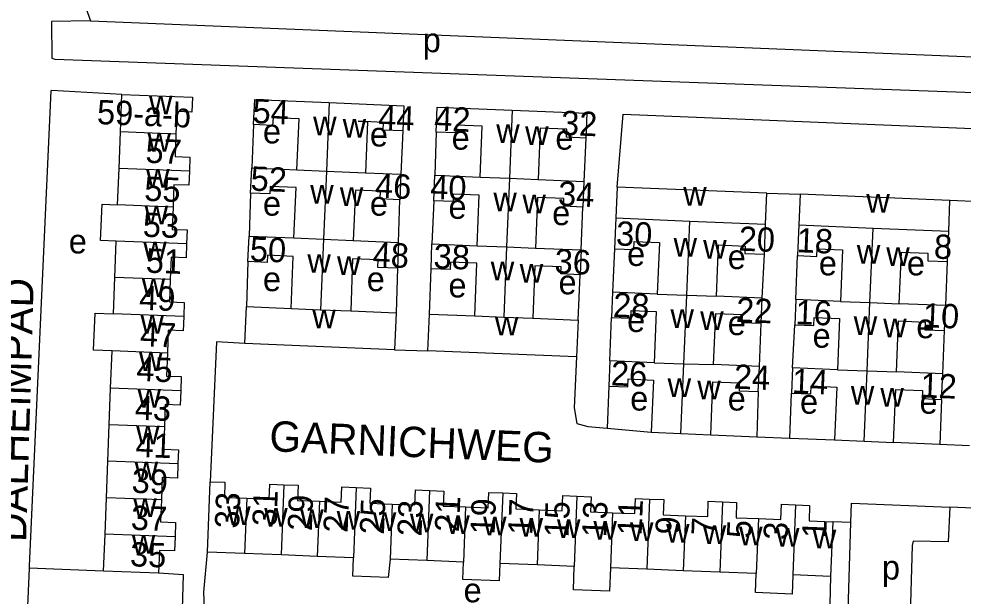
# Model space of a CAD drawing. Extents: x 159675 to 162108, y 386471 to 388472.
# Drawn here: x 161137.4 to 161292.8, y 387294.9 to 387390 of the extents above; entities that cross this region are included whole.
import ezdxf

# ---------------------------------------------------------------- set-up
doc = ezdxf.new("R2010")
doc.units = 0
for name, color, linetype in [('BLT_Basislijn', 7, 'Continuous'), ('BLT_Bebouwing', 7, 'Continuous'), ('BLT_Centroide', 7, 'Continuous'), ('BLT_Huisnummer', 7, 'Continuous'), ('BLT_Huisnummer_ tussenligend', 7, 'Continuous'), ('BLT_Huisnummer_reeks', 7, 'Continuous'), ('BLT_Onderverdeling_panden', 7, 'Continuous'), ('BLT_Straatnaam', 7, 'Continuous')]:
    doc.layers.add(name, color=color, linetype=linetype)

msp = doc.modelspace()

# ---------------------------------------------------------------- linework, layer by layer
at = {"layer": 'BLT_Basislijn'}
for p, q in [((161176.07, 387372.58), (161175.75, 387365.43)), ((161200.64, 387371.53), (161200.31, 387364.39)), ((161206.11, 387371.32), (161205.89, 387364.23)), ((161230.76, 387370.36), (161230.42, 387363.21)), ((161175.57, 387361.3), (161175.32, 387354.22)), ((161199.92, 387353.15), (161200.13, 387360.2)), ((161205.72, 387360.03), (161205.42, 387352.93)), ((161260.53, 387361.25), (161266.01, 387361.12)), ((161295.65, 387359.83), (161290.66, 387360.08)), ((161229.96, 387351.92), (161230.25, 387358.99)), ((161235.45, 387352.12), (161235.12, 387344.96)), ((161259.77, 387343.98), (161260.11, 387351.21)), ((161265.27, 387343.75), (161265.57, 387350.99)), ((161175.14, 387350), (161174.87, 387342.59)), ((161199.74, 387348.92), (161199.5, 387341.58)), ((161289.95, 387342.76), (161290.24, 387350.01)), ((161205.01, 387341.37), (161205.26, 387348.84)), ((161229.45, 387340.37), (161229.79, 387347.84)), ((161234.7, 387333.67), (161234.95, 387340.8)), ((161259.29, 387332.72), (161259.6, 387339.86)), ((161264.76, 387332.52), (161265.1, 387339.62)), ((161289.46, 387331.55), (161289.78, 387338.64)), ((161199.24, 387335.48), (161204.76, 387335.3)), ((161234.53, 387329.52), (161234.23, 387322.57)), ((161259.12, 387328.6), (161258.86, 387321.18)), ((161264.32, 387320.95), (161264.58, 387328.36)), ((161289.28, 387327.31), (161289.01, 387319.89)), ((161234.23, 387322.57), (161241.49, 387321.9)), ((161251.28, 387321.49), (161258.86, 387321.18)), ((161258.86, 387321.18), (161264.32, 387320.95)), ((161264.32, 387320.95), (161271.65, 387320.65)), ((161289.01, 387319.89), (161281.39, 387320.24)), ((161293.86, 387319.67), (161289.01, 387319.89)), ((161294.53, 387309.39), (161290.66, 387309.56)), ((161274.34, 387307.04), (161271.37, 387307.16)), ((161151.39, 387299.04), (161139.11, 387299.54))]:
    msp.add_line(p, q, dxfattribs=at)
for points in [[(160943.5, 387353.98), (160945.17, 387394.9), (160947.37, 387399.46), (160951.35, 387402.23), (160955.9, 387402.72), (161141.02, 387395.32), (161146.97, 387394.51), (161147.64, 387394.14), (161149.23, 387389.66)], [(161149.23, 387389.66), (161142.83, 387389.53), (161142.86, 387383.48), (161143.34, 387383.32), (161329.43, 387376.61)], [(161149.23, 387389.66), (161321.37, 387382.61), (161327.05, 387381.96), (161329.39, 387380.73), (161329.43, 387376.61)], [(161154.39, 387377.51), (161142.88, 387378.21), (161142.67, 387378.11), (161139.12, 387299.91), (161139.11, 387299.54)], [(161235.88, 387362.29), (161236.9, 387374.26), (161329.2, 387370.52)], [(161174.61, 387336.52), (161169.96, 387336.82), (161168.93, 387313.77)], [(161229.21, 387334.31), (161228.82, 387325.91), (161229.25, 387323.37), (161231.09, 387322.86), (161234.23, 387322.57)], [(161274.34, 387307.04), (161274.43, 387310.23), (161290.66, 387309.56)], [(161290.66, 387309.56), (161290.38, 387303.88), (161284.59, 387303.95), (161284.42, 387303.27), (161284.04, 387289.91), (161289.54, 387289.57), (161289.38, 387284.73), (161273.71, 387285.32), (161274.34, 387307.04)], [(161271.02, 387298.17), (161270.75, 387289.03), (161268.09, 387286.92), (161170.87, 387290.42), (161169.76, 387290.68), (161167.96, 387292.87), (161167.85, 387295.57), (161168.48, 387302.18)], [(161139.11, 387299.54), (161138.63, 387288.23), (161164.2, 387287.11), (161164.51, 387298.44), (161160.44, 387298.7)]]:
    msp.add_lwpolyline(points, dxfattribs=at)
at = {"layer": 'BLT_Bebouwing'}
for p, q in [((161154.15, 387371.36), (161154.39, 387377.51)), ((161153.92, 387365.33), (161154.15, 387371.36)), ((161153.69, 387359.34), (161153.92, 387365.33)), ((161175.57, 387361.3), (161175.75, 387365.43)), ((161175.75, 387365.43), (161183.18, 387365.11)), ((161200.31, 387364.39), (161200.13, 387360.2)), ((161205.72, 387360.03), (161205.89, 387364.23)), ((161205.89, 387364.23), (161213.36, 387363.93)), ((161222.87, 387363.52), (161230.42, 387363.21)), ((161230.42, 387363.21), (161230.25, 387358.99)), ((161235.88, 387362.29), (161235.67, 387357.2)), ((161260.53, 387361.25), (161235.88, 387362.29)), ((161260.32, 387356.16), (161260.53, 387361.25)), ((161266.01, 387361.12), (161265.79, 387356.06)), ((161290.66, 387360.08), (161266.01, 387361.12)), ((161290.45, 387355.01), (161290.66, 387360.08)), ((161235.67, 387357.2), (161235.45, 387352.12)), ((161260.11, 387351.21), (161260.32, 387356.16)), ((161265.79, 387356.06), (161265.57, 387350.99)), ((161175.14, 387350), (161175.32, 387354.22)), ((161175.32, 387354.22), (161182.71, 387353.91)), ((161290.24, 387350.01), (161290.45, 387355.01)), ((161153.24, 387347.41), (161153.46, 387353.37)), ((161192.46, 387353.47), (161199.92, 387353.15)), ((161199.92, 387353.15), (161199.74, 387348.92)), ((161205.26, 387348.84), (161205.42, 387352.93)), ((161205.42, 387352.93), (161212.86, 387352.63)), ((161222.44, 387352.22), (161229.96, 387351.92)), ((161229.96, 387351.92), (161229.79, 387347.84)), ((161153.01, 387341.4), (161153.24, 387347.41)), ((161235.12, 387344.96), (161234.95, 387340.8)), ((161242.48, 387344.65), (161235.12, 387344.96)), ((161259.77, 387343.98), (161252.22, 387344.3)), ((161259.6, 387339.86), (161259.77, 387343.98)), ((161265.27, 387343.75), (161265.1, 387339.62)), ((161272.62, 387343.44), (161265.27, 387343.75)), ((161289.95, 387342.76), (161282.32, 387343.08)), ((161289.78, 387338.64), (161289.95, 387342.76)), ((161174.61, 387336.52), (161174.87, 387342.59)), ((161174.87, 387342.59), (161182.22, 387342.27)), ((161192.04, 387341.91), (161199.5, 387341.58)), ((161199.5, 387341.58), (161199.24, 387335.48)), ((161204.76, 387335.3), (161205.01, 387341.37)), ((161205.01, 387341.37), (161212.46, 387341.07)), ((161222.01, 387340.67), (161229.45, 387340.37)), ((161229.45, 387340.37), (161229.21, 387334.31)), ((161199.24, 387335.48), (161174.61, 387336.52)), ((161152.54, 387329.16), (161152.77, 387335.29)), ((161229.21, 387334.31), (161204.76, 387335.3)), ((161234.7, 387333.67), (161234.53, 387329.52)), ((161241.97, 387333.36), (161234.7, 387333.67)), ((161259.29, 387332.72), (161251.76, 387333.04)), ((161259.12, 387328.6), (161259.29, 387332.72)), ((161264.76, 387332.52), (161264.58, 387328.36)), ((161272.14, 387332.21), (161264.76, 387332.52)), ((161289.46, 387331.55), (161281.84, 387331.88)), ((161289.28, 387327.31), (161289.46, 387331.55)), ((161152.31, 387323.13), (161152.54, 387329.16)), ((161152.08, 387317.12), (161152.31, 387323.13)), ((161241.49, 387321.9), (161246.38, 387321.69)), ((161246.38, 387321.69), (161251.28, 387321.49)), ((161271.65, 387320.65), (161276.52, 387320.44)), ((161276.52, 387320.44), (161281.39, 387320.24)), ((161168.48, 387302.18), (161168.93, 387313.77)), ((161151.62, 387305.15), (161151.85, 387311.13)), ((161271.37, 387307.16), (161271.02, 387298.17)), ((161151.39, 387299.04), (161151.62, 387305.15)), ((161174.58, 387301.94), (161168.48, 387302.18)), ((161180.6, 387301.7), (161174.58, 387301.94)), ((161186.53, 387301.47), (161180.6, 387301.7)), ((161192.48, 387301.24), (161186.53, 387301.47)), ((161204.58, 387300.77), (161198.54, 387301)), ((161210.61, 387300.53), (161204.58, 387300.77)), ((161222.7, 387300.06), (161216.6, 387300.3)), ((161228.83, 387299.82), (161222.7, 387300.06)), ((161240.77, 387299.35), (161234.79, 387299.58)), ((161246.76, 387299.11), (161240.77, 387299.35)), ((161160.44, 387298.7), (161151.39, 387299.04)), ((161252.76, 387298.88), (161246.76, 387299.11)), ((161258.78, 387298.65), (161252.76, 387298.88)), ((161271.02, 387298.17), (161264.8, 387298.41))]:
    msp.add_line(p, q, dxfattribs=at)
for points in [[(161154.39, 387377.51), (161166.01, 387377.06), (161165.92, 387374.61), (161163.43, 387374.71), (161163.29, 387371.01)], [(161176.07, 387372.58), (161176.24, 387376.7), (161188.52, 387376.18)], [(161188.52, 387376.18), (161200.81, 387375.66), (161200.64, 387371.53)], [(161206.11, 387371.32), (161206.28, 387375.43), (161218.6, 387374.93)], [(161218.6, 387374.93), (161230.92, 387374.43), (161230.76, 387370.36)], [(161183.18, 387365.11), (161183.54, 387373.51), (161179.26, 387373.69), (161179.2, 387372.44), (161176.07, 387372.58)], [(161200.64, 387371.53), (161197.4, 387371.67), (161197.46, 387372.93), (161193.27, 387373.11), (161194.81, 387373.04), (161194.45, 387364.64)], [(161213.36, 387363.93), (161213.7, 387372.32), (161209.38, 387372.5), (161209.33, 387371.19), (161206.11, 387371.32)], [(161163.29, 387371.01), (161163.15, 387367.3), (161165.59, 387367.21), (161165.5, 387364.89)], [(161230.76, 387370.36), (161227.56, 387370.49), (161227.61, 387371.79), (161223.21, 387371.97), (161222.87, 387363.52)], [(161165.5, 387364.89), (161165.41, 387362.58), (161162.96, 387362.67), (161162.81, 387358.99)], [(161194.45, 387364.64), (161200.31, 387364.39)], [(161182.71, 387353.91), (161183.07, 387362.21), (161178.81, 387362.39), (161178.76, 387361.16), (161175.57, 387361.3)], [(161200.13, 387360.2), (161196.91, 387360.33), (161196.96, 387361.6), (161192.81, 387361.78), (161192.46, 387353.47)], [(161212.86, 387352.63), (161213.2, 387360.93), (161208.93, 387361.11), (161208.88, 387359.9), (161205.72, 387360.03)], [(161230.25, 387358.99), (161227.09, 387359.12), (161227.14, 387360.4), (161222.77, 387360.57), (161222.44, 387352.22)], [(161153.46, 387353.37), (161150.89, 387353.47), (161151.12, 387359.44), (161153.69, 387359.34)], [(161162.81, 387358.99), (161162.67, 387355.31), (161165.12, 387355.22), (161165.03, 387352.93)], [(161165.03, 387352.93), (161164.94, 387350.64), (161162.48, 387350.73), (161162.34, 387347.06)], [(161235.45, 387352.12), (161238.63, 387351.98), (161238.68, 387353.32), (161242.84, 387353.15), (161242.48, 387344.65)], [(161252.22, 387344.3), (161252.57, 387352.75), (161256.95, 387352.57), (161256.9, 387351.34), (161260.11, 387351.21)], [(161265.57, 387350.99), (161268.73, 387350.86), (161268.79, 387352.1), (161272.98, 387351.92), (161272.62, 387343.44)], [(161182.22, 387342.27), (161182.58, 387350.87), (161178.34, 387351.05), (161178.29, 387349.87), (161175.14, 387350)], [(161199.74, 387348.92), (161196.52, 387349.05), (161196.57, 387350.31), (161192.34, 387350.49), (161192.04, 387341.91)], [(161282.32, 387343.08), (161282.68, 387351.58), (161287.04, 387351.39), (161286.99, 387350.15), (161290.24, 387350.01)], [(161212.46, 387341.07), (161212.82, 387349.77), (161208.48, 387349.91), (161208.43, 387348.71), (161205.26, 387348.84)], [(161229.79, 387347.84), (161226.63, 387347.97), (161226.68, 387349.15), (161222.36, 387349.33), (161222.01, 387340.67)], [(161162.34, 387347.06), (161162.2, 387343.39), (161164.66, 387343.3), (161164.57, 387340.96)], [(161152.77, 387335.29), (161149.73, 387335.4), (161149.97, 387341.52), (161153.01, 387341.4)], [(161234.95, 387340.8), (161238.14, 387340.67), (161238.2, 387341.98), (161242.32, 387341.8), (161241.97, 387333.36)], [(161251.76, 387333.04), (161252.11, 387341.48), (161256.45, 387341.3), (161256.39, 387339.99), (161259.6, 387339.86)], [(161164.57, 387340.96), (161164.48, 387338.62), (161162.03, 387338.72), (161161.89, 387334.94)], [(161265.1, 387339.62), (161268.26, 387339.49), (161268.31, 387340.82), (161272.5, 387340.64), (161272.14, 387332.21)], [(161281.84, 387331.88), (161282.19, 387340.23), (161286.57, 387340.05), (161286.52, 387338.78), (161289.78, 387338.64)], [(161161.89, 387334.94), (161161.74, 387331.16), (161164.16, 387331.07), (161164.07, 387328.72)], [(161234.53, 387329.52), (161237.67, 387329.38), (161237.72, 387330.69), (161241.85, 387330.51), (161241.49, 387321.9)], [(161251.28, 387321.49), (161251.65, 387330.23), (161255.99, 387330.04), (161255.94, 387328.73), (161259.12, 387328.6)], [(161164.07, 387328.72), (161163.98, 387326.36), (161161.52, 387326.46), (161161.38, 387322.79)], [(161264.58, 387328.36), (161267.77, 387328.22), (161267.82, 387329.53), (161272.02, 387329.35), (161271.65, 387320.65)], [(161281.39, 387320.24), (161281.76, 387328.96), (161286.12, 387328.78), (161286.06, 387327.44), (161289.28, 387327.31)], [(161161.38, 387322.79), (161161.24, 387319.12), (161163.71, 387319.02), (161163.62, 387316.68)], [(161151.85, 387311.13), (161152.08, 387317.12)], [(161163.62, 387316.68), (161163.53, 387314.34), (161161.03, 387314.43), (161160.89, 387310.79)], [(161168.93, 387313.77), (161171.34, 387313.67), (161171.25, 387311.18), (161174.94, 387311.03)], [(161174.94, 387311.03), (161178.63, 387310.89), (161178.72, 387313.36), (161181.05, 387313.27)], [(161181.05, 387313.27), (161183.37, 387313.18), (161183.27, 387310.68), (161186.89, 387310.54)], [(161186.89, 387310.54), (161190.5, 387310.4), (161190.6, 387312.9), (161192.94, 387312.8)], [(161192.94, 387312.8), (161195.28, 387312.71), (161195.18, 387310.22), (161198.89, 387310.08)], [(161198.89, 387310.08), (161202.61, 387309.93), (161202.7, 387312.41), (161205.03, 387312.31)], [(161205.03, 387312.31), (161207.36, 387312.22), (161207.27, 387309.75), (161210.96, 387309.61)], [(161210.96, 387309.61), (161214.66, 387309.47), (161214.76, 387312), (161217.05, 387311.91)], [(161217.05, 387311.91), (161219.34, 387311.82), (161219.24, 387309.28), (161223.05, 387309.14)], [(161160.89, 387310.79), (161160.75, 387307.15), (161163.22, 387307.05), (161163.13, 387304.71)], [(161223.05, 387309.14), (161226.86, 387308.99), (161226.96, 387311.48), (161229.28, 387311.39)], [(161229.28, 387311.39), (161231.6, 387311.3), (161231.5, 387308.79), (161235.15, 387308.65)], [(161235.15, 387308.65), (161238.8, 387308.51), (161238.89, 387310.99), (161241.22, 387310.9)], [(161241.22, 387310.9), (161243.55, 387310.81), (161243.45, 387308.3), (161247.12, 387308.16)], [(161247.12, 387308.16), (161250.79, 387308.01), (161250.89, 387310.54), (161253.21, 387310.45)], [(161253.21, 387310.45), (161255.54, 387310.36), (161255.45, 387307.83), (161259.14, 387307.68)], [(161259.14, 387307.68), (161262.83, 387307.54), (161262.93, 387310.04), (161265.24, 387309.95)], [(161265.24, 387309.95), (161267.56, 387309.86), (161267.46, 387307.32), (161271.37, 387307.16)], [(161163.13, 387304.71), (161163.05, 387302.37), (161160.59, 387302.46), (161160.44, 387298.7)], [(161198.54, 387301), (161198.23, 387297.99), (161192.37, 387298.22), (161192.48, 387301.24)], [(161216.6, 387300.3), (161216.49, 387297.45), (161210.47, 387297.68), (161210.61, 387300.53)], [(161234.79, 387299.58), (161234.64, 387295.73), (161228.68, 387295.96), (161228.83, 387299.82)], [(161264.8, 387298.41), (161264.67, 387295.27), (161258.66, 387295.5), (161258.78, 387298.65)]]:
    msp.add_lwpolyline(points, dxfattribs=at)
at = {"layer": 'BLT_Onderverdeling_panden'}
for p, q in [((161188.52, 387376.18), (161188.05, 387364.91)), ((161218.6, 387374.93), (161218.15, 387363.72)), ((161163.29, 387371.01), (161154.15, 387371.36)), ((161165.5, 387364.89), (161153.92, 387365.33)), ((161183.18, 387365.11), (161188.05, 387364.91)), ((161188.05, 387364.91), (161187.57, 387353.69)), ((161188.05, 387364.91), (161194.45, 387364.64)), ((161213.36, 387363.93), (161218.15, 387363.72)), ((161218.15, 387363.72), (161217.69, 387352.42)), ((161218.15, 387363.72), (161222.87, 387363.52)), ((161162.81, 387358.99), (161153.69, 387359.34)), ((161235.67, 387357.2), (161247.85, 387356.69)), ((161247.34, 387344.48), (161247.85, 387356.69)), ((161247.85, 387356.69), (161260.32, 387356.16)), ((161265.79, 387356.06), (161278.01, 387355.54)), ((161277.49, 387343.26), (161278.01, 387355.54)), ((161278.01, 387355.54), (161290.45, 387355.01)), ((161182.71, 387353.91), (161187.57, 387353.69)), ((161187.57, 387353.69), (161187.08, 387342.09)), ((161187.57, 387353.69), (161192.46, 387353.47)), ((161165.03, 387352.93), (161153.46, 387353.37)), ((161212.86, 387352.63), (161217.69, 387352.42)), ((161217.69, 387352.42), (161217.23, 387340.87)), ((161217.69, 387352.42), (161222.44, 387352.22)), ((161162.34, 387347.06), (161153.24, 387347.41)), ((161242.48, 387344.65), (161247.34, 387344.48)), ((161246.87, 387333.2), (161247.34, 387344.48)), ((161247.34, 387344.48), (161252.22, 387344.3)), ((161272.62, 387343.44), (161277.49, 387343.26)), ((161277.01, 387332.04), (161277.49, 387343.26)), ((161277.49, 387343.26), (161282.32, 387343.08)), ((161164.57, 387340.96), (161153.01, 387341.4)), ((161182.22, 387342.27), (161187.08, 387342.09)), ((161187.08, 387342.09), (161192.04, 387341.91)), ((161212.46, 387341.07), (161217.23, 387340.87)), ((161217.23, 387340.87), (161222.01, 387340.67)), ((161161.89, 387334.94), (161152.77, 387335.29)), ((161241.97, 387333.36), (161246.87, 387333.2)), ((161246.38, 387321.69), (161246.87, 387333.2)), ((161246.87, 387333.2), (161251.76, 387333.04)), ((161272.14, 387332.21), (161277.01, 387332.04)), ((161276.52, 387320.44), (161277.01, 387332.04)), ((161277.01, 387332.04), (161281.84, 387331.88)), ((161164.07, 387328.72), (161152.54, 387329.16)), ((161161.38, 387322.79), (161152.31, 387323.13)), ((161163.62, 387316.68), (161152.08, 387317.12)), ((161181.05, 387313.27), (161180.6, 387301.7)), ((161192.94, 387312.8), (161192.48, 387301.24)), ((161205.03, 387312.31), (161204.58, 387300.77)), ((161217.05, 387311.91), (161216.6, 387300.3)), ((161160.89, 387310.79), (161151.85, 387311.13)), ((161174.94, 387311.03), (161174.58, 387301.94)), ((161186.89, 387310.54), (161186.53, 387301.47)), ((161198.89, 387310.08), (161198.54, 387301)), ((161229.28, 387311.39), (161228.83, 387299.82)), ((161241.22, 387310.9), (161240.77, 387299.35)), ((161253.21, 387310.45), (161252.76, 387298.88)), ((161210.96, 387309.61), (161210.61, 387300.53)), ((161223.05, 387309.14), (161222.7, 387300.06)), ((161235.15, 387308.65), (161234.79, 387299.58)), ((161265.24, 387309.95), (161264.8, 387298.41)), ((161247.12, 387308.16), (161246.76, 387299.11)), ((161259.14, 387307.68), (161258.78, 387298.65)), ((161163.13, 387304.71), (161151.62, 387305.15))]:
    msp.add_line(p, q, dxfattribs=at)

# ---------------------------------------------------------------- texts
at = {"layer": 'BLT_Centroide'}
for s, p in [('p', (161203.9, 387384.49)), ('w', (161158.84, 387374.25)), ('w', (161185.86, 387370.81)), ('e', (161177.6, 387369.47)), ('w', (161190.72, 387370.44)), ('w', (161215.99, 387369.56)), ('w', (161220.74, 387369.22)), ('w', (161158.6, 387368.12)), ('e', (161195.2, 387368.96)), ('e', (161208.65, 387368.44)), ('e', (161225.72, 387368.44)), ('w', (161158.37, 387362.16)), ('w', (161185.38, 387359.56)), ('w', (161190.25, 387359.19)), ('w', (161215.52, 387358.31)), ('w', (161246.76, 387359.22)), ('e', (161177.6, 387357.57)), ('e', (161195.2, 387357.57)), ('e', (161208.13, 387357.05)), ('w', (161220.3, 387357.97)), ('w', (161276.89, 387358.06)), ('w', (161158.13, 387356.12)), ('e', (161225.2, 387356.01)), ('e', (161145.65, 387351.35)), ('w', (161245.17, 387350.84)), ('w', (161250.04, 387350.5)), ('w', (161157.9, 387350.22)), ('e', (161237.52, 387349.29)), ('w', (161275.33, 387349.66)), ('w', (161280.17, 387349.31)), ('w', (161184.91, 387348.16)), ('w', (161189.79, 387347.81)), ('e', (161254.08, 387348.78)), ('e', (161269.08, 387347.74)), ('e', (161283.57, 387347.74)), ('w', (161215.09, 387346.91)), ('w', (161219.85, 387346.53)), ('e', (161177.6, 387345.14)), ('e', (161194.68, 387345.14)), ('e', (161226.24, 387344.62)), ('w', (161157.66, 387344.19)), ('e', (161208.13, 387344.11)), ('w', (161157.45, 387338.16)), ('w', (161185.72, 387339.03)), ('e', (161237.52, 387338.42)), ('w', (161244.66, 387339.09)), ('w', (161249.55, 387338.75)), ('w', (161215.77, 387337.84)), ('e', (161254.08, 387337.9)), ('w', (161274.82, 387337.91)), ('w', (161279.66, 387337.56)), ('e', (161285.12, 387337.39)), ('e', (161268.05, 387335.83)), ('w', (161157.22, 387332)), ('w', (161244.19, 387327.69)), ('w', (161249.08, 387327.34)), ('w', (161156.96, 387325.97)), ('w', (161274.34, 387326.47)), ('w', (161279.2, 387326.12)), ('e', (161238.04, 387325.48)), ('e', (161254.08, 387325.48)), ('e', (161265.98, 387324.96)), ('e', (161285.64, 387324.96)), ('w', (161156.73, 387319.91)), ('w', (161156.48, 387313.97)), ('w', (161156.26, 387307.94)), ('w', (161171.7, 387306.61)), ('w', (161177.81, 387306.36)), ('w', (161183.73, 387306.12)), ('w', (161189.73, 387305.89)), ('w', (161195.69, 387305.67)), ('w', (161201.78, 387305.42)), ('w', (161207.77, 387305.17)), ('w', (161213.83, 387304.95)), ('w', (161219.83, 387304.7)), ('w', (161225.98, 387304.48)), ('w', (161231.98, 387304.23)), ('w', (161238, 387304)), ('w', (161243.94, 387303.75)), ('w', (161249.98, 387303.52)), ('w', (161255.95, 387303.28)), ('w', (161262.02, 387303.05)), ('w', (161268.08, 387302.78)), ('w', (161156.03, 387301.94)), ('p', (161279.46, 387297.65)), ('e', (161210.62, 387293.9))]:
    msp.add_text(s, height=4, dxfattribs=at).set_placement(p)
at = {"layer": 'BLT_Huisnummer'}
for s, rotation, p in [('54', 357.6549, (161175.84, 387372.83)), ('44', 357.6549, (161196.51, 387371.8)), ('42', 357.6549, (161205.72, 387371.6)), ('32', 357.6549, (161226.59, 387370.88)), ('52', 357.6549, (161175.51, 387361.71)), ('46', 357.6549, (161195.99, 387360.55)), ('55', 357.8173, (161158.02, 387360.03)), ('40', 357.6549, (161205.07, 387360.34)), ('34', 357.6549, (161226.11, 387359.23)), ('30', 357.6549, (161235.65, 387352.67)), ('20', 357.6549, (161255.83, 387351.82)), ('18', 357.6549, (161265.38, 387351.56)), ('50', 357.6549, (161175.39, 387350.09)), ('8', 357.6549, (161287.96, 387350.52)), ('51', 357.8173, (161158.27, 387348.2)), ('48', 357.6549, (161195.6, 387349.2)), ('38', 357.6549, (161205.62, 387348.93)), ('36', 357.6549, (161225.54, 387348.11)), ('28', 357.6549, (161235.16, 387340.9)), ('22', 357.6549, (161255.39, 387340.08)), ('16', 357.6549, (161265.19, 387339.71)), ('10', 357.6549, (161286.14, 387339.21)), ('47', 357.8173, (161157.32, 387336.08)), ('26', 357.6549, (161234.8, 387329.64)), ('24', 357.6549, (161255.03, 387329.1)), ('14', 357.6549, (161264.6, 387328.38)), ('12', 357.6549, (161285.75, 387327.67)), ('43', 357.8173, (161156.47, 387323.98)), ('39', 357.8173, (161155.95, 387311.95)), ('33', 87.7597, (161173.66, 387306.01)), ('29', 87.7597, (161185.64, 387305.6)), ('25', 87.7597, (161197.51, 387305.01)), ('21', 87.7597, (161209.86, 387305.41)), ('17', 87.7597, (161221.93, 387304.93)), ('13', 87.7597, (161234.1, 387304.55)), ('9', 87.7597, (161246.16, 387305)), ('5', 87.7597, (161257.93, 387304.4)), ('1', 87.7597, (161270.28, 387304.4)), ('35', 357.8173, (161155.68, 387299.85))]:
    msp.add_text(s, height=4, rotation=rotation, dxfattribs=at).set_placement(p)
at = {"layer": 'BLT_Huisnummer_ tussenligend'}
for s, rotation, p in [('57', 357.8173, (161158.22, 387366.29)), ('53', 357.8173, (161157.78, 387354.11)), ('49', 357.8173, (161157.18, 387342.09)), ('45', 357.8173, (161156.73, 387330.36)), ('41', 357.8173, (161156.58, 387317.87)), ('31', 87.7597, (161179.83, 387306.37)), ('27', 87.7597, (161191.53, 387305.3)), ('23', 87.7597, (161203.69, 387304.71)), ('19', 87.7597, (161215.72, 387305)), ('15', 87.7597, (161227.88, 387304.55)), ('11', 87.7597, (161239.91, 387304.85)), ('37', 357.8173, (161155.82, 387305.86)), ('7', 87.7597, (161252.09, 387304.84)), ('3', 87.7597, (161263.95, 387304.11))]:
    msp.add_text(s, height=4, rotation=rotation, dxfattribs=at).set_placement(p)
at = {"layer": 'BLT_Huisnummer_reeks'}
msp.add_text('59-a-b', height=4, rotation=357.8173, dxfattribs=at).set_placement((161150.24, 387372.66))
at = {"layer": 'BLT_Straatnaam'}
for s, rotation, p in [('DALHEIMPAD', 88.3146, (161138.62, 387303.79)), ('GARNICHWEG', 357.6251, (161178.59, 387318.8))]:
    msp.add_text(s, height=5, rotation=rotation, dxfattribs=at).set_placement(p)

doc.saveas('drawing.dxf')
